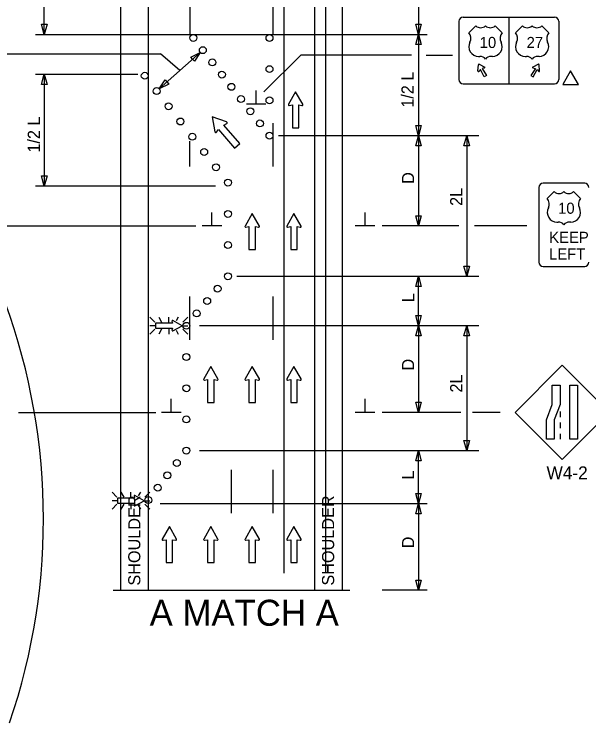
# Model space of a CAD drawing. Extents: x 16512 to 19504, y 5761 to 6984.
# Drawn here: x 16825.1 to 17156.7, y 5982.1 to 6390.9 of the extents above; entities that cross this region are included whole.
import ezdxf

# ---------------------------------------------------------------- set-up
doc = ezdxf.new("R2010")
doc.units = 0
for name, color, linetype in [('ALI_LEGAL_EX', 7, 'Continuous'), ('Level 3', 7, 'Continuous'), ('MT_SCRATCH_LEVEL_E', 7, 'Continuous'), ('PAVT_EDGE_EX', 7, 'Continuous'), ('TRAFFIC_SIGNS_PR', 7, 'Continuous'), ('TYPICAL_EX', 7, 'Continuous'), ('TYPICAL_TEXT_DIMEN_PR', 7, 'Continuous')]:
    doc.layers.add(name, color=color, linetype=linetype)

msp = doc.modelspace()

# ---------------------------------------------------------------- linework, layer by layer
at = {"layer": 'ALI_LEGAL_EX'}
for p, q in [((16980.68, 6984.25), (16980.68, 6166.11)), ((17004.68, 6984.25), (17004.68, 6166.11)), ((16980.68, 6932.34), (16980.68, 6068.43)), ((17004.68, 6932.34), (17004.68, 6068.43))]:
    msp.add_line(p, q, dxfattribs=at)
for points in [[(16974.45, 6302.95), (16974.45, 6327.95)], [(16926.45, 6302.95), (16926.45, 6317.59)], [(16926.45, 6202.95), (16926.45, 6227.95)], [(16974.45, 6202.95), (16974.45, 6227.95)], [(16950.45, 6102.95), (16950.45, 6127.95)], [(16974.45, 6102.95), (16974.45, 6127.95)]]:
    msp.add_lwpolyline(points, dxfattribs=at)
msp.add_arc((16477.95, 6099.7), 364, 341.1459, 21.3367, dxfattribs=at)
at = {"layer": 'Level 3'}
msp.add_line((16842.45, 6379.15), (16842.45, 6429.22), dxfattribs=at)
at = {"layer": 'MT_SCRATCH_LEVEL_E'}
for p, q in [((16987.48, 6346.14), (16983.37, 6338.9)), ((16991.62, 6338.9), (16987.48, 6346.14)), ((16983.85, 6338.22), (16985.63, 6338.53)), ((16985.63, 6338.53), (16985.63, 6325.28)), ((16989.37, 6325.28), (16989.37, 6338.53)), ((16989.37, 6338.53), (16991.15, 6338.22)), ((16985.63, 6325.28), (16989.37, 6325.28)), ((16962.45, 6275.9), (16958.33, 6268.66)), ((16962.45, 6275.9), (16958.33, 6268.66)), ((16966.59, 6268.66), (16962.45, 6275.9)), ((16966.59, 6268.66), (16962.45, 6275.9)), ((16986.5, 6275.9), (16982.39, 6268.66)), ((16986.5, 6275.9), (16982.39, 6268.66)), ((16990.65, 6268.66), (16986.5, 6275.9)), ((16990.65, 6268.66), (16986.5, 6275.9)), ((16958.82, 6267.97), (16960.59, 6268.29)), ((16958.82, 6267.97), (16960.59, 6268.29)), ((16960.59, 6268.29), (16960.59, 6255.03)), ((16960.59, 6268.29), (16960.59, 6255.03)), ((16964.34, 6255.03), (16964.34, 6268.29)), ((16964.34, 6268.29), (16966.11, 6267.97)), ((16964.34, 6255.03), (16964.34, 6268.29)), ((16964.34, 6268.29), (16966.11, 6267.97)), ((16982.87, 6267.97), (16984.65, 6268.29)), ((16982.87, 6267.97), (16984.65, 6268.29)), ((16984.65, 6268.29), (16984.65, 6255.03)), ((16984.65, 6268.29), (16984.65, 6255.03)), ((16988.39, 6255.03), (16988.39, 6268.29)), ((16988.39, 6268.29), (16990.17, 6267.97)), ((16988.39, 6255.03), (16988.39, 6268.29)), ((16988.39, 6268.29), (16990.17, 6267.97)), ((16960.59, 6255.03), (16964.34, 6255.03)), ((16960.59, 6255.03), (16964.34, 6255.03)), ((16984.65, 6255.03), (16988.39, 6255.03)), ((16984.65, 6255.03), (16988.39, 6255.03)), ((16938.54, 6187.65), (16934.43, 6180.41)), ((16942.69, 6180.41), (16938.54, 6187.65)), ((16962.45, 6187.65), (16958.33, 6180.41)), ((16966.59, 6180.41), (16962.45, 6187.65)), ((16986.5, 6187.65), (16982.39, 6180.41)), ((16990.65, 6180.41), (16986.5, 6187.65)), ((16934.91, 6179.73), (16936.69, 6180.04)), ((16936.69, 6180.04), (16936.69, 6166.78)), ((16940.43, 6166.78), (16940.43, 6180.04)), ((16940.43, 6180.04), (16942.21, 6179.73)), ((16958.82, 6179.73), (16960.59, 6180.04)), ((16960.59, 6180.04), (16960.59, 6166.78)), ((16964.34, 6166.78), (16964.34, 6180.04)), ((16964.34, 6180.04), (16966.11, 6179.73)), ((16982.87, 6179.73), (16984.65, 6180.04)), ((16984.65, 6180.04), (16984.65, 6166.78)), ((16988.39, 6166.78), (16988.39, 6180.04)), ((16988.39, 6180.04), (16990.17, 6179.73)), ((16936.69, 6166.78), (16940.43, 6166.78)), ((16960.59, 6166.78), (16964.34, 6166.78)), ((16984.65, 6166.78), (16988.39, 6166.78)), ((16914.64, 6095.33), (16910.53, 6088.09)), ((16918.78, 6088.09), (16914.64, 6095.33)), ((16938.54, 6095.33), (16934.43, 6088.09)), ((16942.69, 6088.09), (16938.54, 6095.33)), ((16962.45, 6095.33), (16958.33, 6088.09)), ((16966.59, 6088.09), (16962.45, 6095.33)), ((16986.5, 6095.33), (16982.39, 6088.09)), ((16990.65, 6088.09), (16986.5, 6095.33)), ((16911.01, 6087.41), (16912.79, 6087.72)), ((16912.79, 6087.72), (16912.79, 6074.47)), ((16916.53, 6074.47), (16916.53, 6087.72)), ((16916.53, 6087.72), (16918.31, 6087.41)), ((16934.91, 6087.41), (16936.69, 6087.72)), ((16936.69, 6087.72), (16936.69, 6074.47)), ((16940.43, 6074.47), (16940.43, 6087.72)), ((16940.43, 6087.72), (16942.21, 6087.41)), ((16958.82, 6087.41), (16960.59, 6087.72)), ((16960.59, 6087.72), (16960.59, 6074.47)), ((16964.34, 6074.47), (16964.34, 6087.72)), ((16964.34, 6087.72), (16966.11, 6087.41)), ((16982.87, 6087.41), (16984.65, 6087.72)), ((16984.65, 6087.72), (16984.65, 6074.47)), ((16988.39, 6074.47), (16988.39, 6087.72)), ((16988.39, 6087.72), (16990.17, 6087.41)), ((16912.79, 6074.47), (16916.53, 6074.47)), ((16936.69, 6074.47), (16940.43, 6074.47)), ((16960.59, 6074.47), (16964.34, 6074.47)), ((16984.65, 6074.47), (16988.39, 6074.47))]:
    msp.add_line(p, q, dxfattribs=at)
for centre, start, end in [((16983.77, 6338.68), 150.4248, 279.9638), ((16991.22, 6338.68), 260.0362, 29.7731), ((16958.74, 6268.43), 150.4248, 279.9638), ((16958.74, 6268.43), 150.4248, 279.9638), ((16966.18, 6268.43), 260.0362, 29.7731), ((16966.18, 6268.43), 260.0362, 29.7731), ((16982.8, 6268.43), 150.4248, 279.9638), ((16982.8, 6268.43), 150.4248, 279.9638), ((16990.24, 6268.43), 260.0362, 29.7731), ((16990.24, 6268.43), 260.0362, 29.7731), ((16934.84, 6180.19), 150.4248, 279.9638), ((16942.28, 6180.19), 260.0362, 29.7731), ((16958.74, 6180.19), 150.4248, 279.9638), ((16966.18, 6180.19), 260.0362, 29.7731), ((16982.8, 6180.19), 150.4248, 279.9638), ((16990.24, 6180.19), 260.0362, 29.7731), ((16910.93, 6087.87), 150.4248, 279.9638), ((16918.38, 6087.87), 260.0362, 29.7731), ((16934.84, 6087.87), 150.4248, 279.9638), ((16942.28, 6087.87), 260.0362, 29.7731), ((16958.74, 6087.87), 150.4248, 279.9638), ((16966.18, 6087.87), 260.0362, 29.7731), ((16982.8, 6087.87), 150.4248, 279.9638), ((16990.24, 6087.87), 260.0362, 29.7731)]:
    msp.add_arc(centre, 0.463, start, end, dxfattribs=at)
at = {"layer": 'PAVT_EDGE_EX'}
for p, q in [((16886.45, 6490.66), (16886.45, 6058.52)), ((16902.45, 6490.66), (16902.45, 6058.52)), ((16998.45, 6490.66), (16998.45, 6058.52)), ((17014.45, 6490.66), (17014.45, 6058.52))]:
    msp.add_line(p, q, dxfattribs=at)
msp.add_lwpolyline([(16974.45, 6479.22), (16926.45, 6479.22), (16926.45, 6379.15), (16974.45, 6379.15)], close=True, dxfattribs=at)
at = {"layer": 'TRAFFIC_SIGNS_PR'}
for p, q in [((17081.73, 6386.73), (17081.73, 6353.13)), ((17084.13, 6389.13), (17136.93, 6389.13)), ((17110.53, 6389.13), (17110.53, 6350.73)), ((17139.33, 6386.73), (17139.33, 6353.13)), ((17092.71, 6358.08), (17092.99, 6361.71)), ((17093.36, 6361.92), (17096.64, 6360.35)), ((17127.69, 6361.92), (17124.42, 6360.35)), ((17128.35, 6358.08), (17128.07, 6361.71)), ((17084.13, 6350.73), (17136.93, 6350.73)), ((17154.33, 6293.33), (17130.33, 6293.33)), ((17127.94, 6290.93), (17127.94, 6247.73)), ((17130.33, 6245.33), (17154.33, 6245.33)), ((16906.22, 6213.19), (16903.4, 6216.01)), ((16908.52, 6216.01), (16910.15, 6213.19)), ((16914.31, 6213.19), (16914.31, 6216.01)), ((16919.78, 6216.01), (16918.57, 6213.92)), ((16925.21, 6216.01), (16922.39, 6213.19)), ((16906.22, 6211.16), (16903.4, 6211.16)), ((16922.39, 6211.16), (16925.21, 6211.16)), ((16906.22, 6209.12), (16903.4, 6206.3)), ((16910.17, 6209.12), (16908.54, 6206.3)), ((16914.31, 6209.12), (16914.31, 6206.3)), ((16918.49, 6208.49), (16919.75, 6206.3)), ((16925.21, 6206.31), (16922.39, 6209.12)), ((17141.36, 6188.31), (17114.21, 6161.16)), ((17168.51, 6161.16), (17141.36, 6188.31)), ((17114.21, 6161.16), (17141.36, 6134.01)), ((17140.11, 6161.65), (17140.11, 6158.45)), ((17141.36, 6134.01), (17168.51, 6161.16)), ((17140.11, 6155.25), (17140.11, 6152.05)), ((17140.11, 6148.85), (17140.11, 6145.65)), ((16884.35, 6112.24), (16881.53, 6115.06)), ((16886.65, 6115.06), (16888.27, 6112.24)), ((16892.43, 6112.24), (16892.43, 6115.06)), ((16897.9, 6115.06), (16896.69, 6112.96)), ((16903.34, 6115.05), (16900.52, 6112.24)), ((16884.35, 6110.2), (16881.53, 6110.2)), ((16884.35, 6108.17), (16881.53, 6105.35)), ((16888.3, 6108.17), (16886.67, 6105.35)), ((16892.43, 6108.17), (16892.43, 6105.35)), ((16896.62, 6107.54), (16897.88, 6105.35)), ((16900.52, 6110.2), (16903.34, 6110.2)), ((16903.34, 6105.35), (16900.52, 6108.17))]:
    msp.add_line(p, q, dxfattribs=at)
for points in [[(17096.6, 6359.87), (17095.19, 6359.48), (17097.71, 6355.5), (17096.38, 6354.73), (17094.19, 6358.9), (17093.15, 6357.88)], [(17124.46, 6359.87), (17125.87, 6359.48), (17123.35, 6355.5), (17124.68, 6354.73), (17126.87, 6358.9), (17127.91, 6357.88)], [(16916.13, 6213.84), (16916.36, 6212.54), (16906.64, 6212.54), (16906.64, 6209.8), (16916.36, 6209.8), (16916.13, 6208.5)], [(16916.63, 6208.14), (16921.94, 6211.16), (16916.63, 6214.2)], [(16894.26, 6112.89), (16894.49, 6111.59), (16884.77, 6111.59), (16884.77, 6108.85), (16894.49, 6108.85), (16894.26, 6107.54)], [(16894.76, 6107.19), (16900.07, 6110.2), (16894.76, 6113.25)]]:
    msp.add_lwpolyline(points, dxfattribs=at)
for points in [[(17140.11, 6176.9), (17140.11, 6165.72), (17136.77, 6156.83), (17136.77, 6145.65), (17132.27, 6145.65), (17132.27, 6156.83), (17135.62, 6165.72), (17135.62, 6176.9)], [(17150.25, 6176.9), (17150.25, 6145.65), (17145.76, 6145.65), (17145.76, 6176.9)]]:
    msp.add_lwpolyline(points, close=True, dxfattribs=at)
for centre in [(16928.45, 6377.15), (16928.45, 6377.15), (16972.44, 6377.15), (16933.95, 6370.1), (16939.44, 6363.05), (16972.44, 6359.15), (16900.45, 6355.31), (16944.94, 6356), (16907.3, 6346.52), (16950.43, 6348.95), (16955.93, 6341.9), (16972.44, 6341.15), (16914.16, 6337.72), (16961.42, 6334.86), (16921.02, 6328.93), (16966.92, 6327.81), (16927.87, 6320.13), (16972.42, 6320.76), (16934.73, 6311.34), (16941.59, 6302.55), (16948.44, 6293.7), (16948.44, 6275.65), (16948.44, 6257.65), (16948.44, 6239.65), (16942.44, 6232.51), (16936.44, 6225.37), (16930.44, 6218.23), (16924.44, 6211.09), (16924.44, 6193.09), (16924.44, 6175.09), (16924.44, 6157.09), (16924.44, 6139.09), (16918.95, 6131.95), (16913.45, 6124.83), (16907.95, 6117.7), (16902.46, 6110.57)]:
    msp.add_circle(centre, 2, dxfattribs=at)
for centre, radius, start, end in [((17084.13, 6386.73), 2.4, 90, 180), ((17084.13, 6386.73), 2.4, 90, 180), ((17136.93, 6386.73), 2.4, 0, 90), ((17093.25, 6361.69), 0.26, 64.4823, 175.5177), ((17127.81, 6361.69), 0.26, 4.4823, 115.5177), ((17092.97, 6358.06), 0.26, 175.5177, 314.0115), ((17096.53, 6360.12), 0.26, 285.9885, 64.4823), ((17124.53, 6360.12), 0.26, 115.5177, 254.0115), ((17128.09, 6358.06), 0.26, 225.9885, 4.4823), ((17084.13, 6353.13), 2.4, 180, 270), ((17136.93, 6353.13), 2.4, 270, 0), ((17130.33, 6290.93), 2.4, 90, 180), ((17154.33, 6290.93), 2.4, 0, 90), ((17130.33, 6247.73), 2.4, 180, 270), ((17154.33, 6247.73), 2.4, 270, 0), ((16916.47, 6213.9), 0.341, 61.4833, 189.9593), ((16916.47, 6208.44), 0.341, 170.7308, 298.8916), ((16894.6, 6112.95), 0.341, 61.4833, 189.9593), ((16894.6, 6107.49), 0.341, 170.7308, 298.8916)]:
    msp.add_arc(centre, radius, start, end, dxfattribs=at)
at = {"layer": 'TYPICAL_EX'}
for p, q in [((17087.48, 6380.13), (17091.48, 6384.13)), ((17106.68, 6380.13), (17102.68, 6384.13)), ((17114.38, 6380.13), (17118.38, 6384.13)), ((17133.58, 6380.13), (17129.58, 6384.13)), ((17093.07, 6366.52), (17093.87, 6366.52)), ((17101.09, 6366.52), (17100.29, 6366.52)), ((17119.97, 6366.52), (17120.77, 6366.52)), ((17127.99, 6366.52), (17127.19, 6366.52)), ((17132.74, 6284.53), (17136.74, 6288.53)), ((17151.94, 6284.53), (17147.94, 6288.53)), ((17138.33, 6270.92), (17139.13, 6270.92)), ((17146.34, 6270.92), (17145.54, 6270.92))]:
    msp.add_line(p, q, dxfattribs=at)
for centre, radius, start, end in [((17094.28, 6387.05), 4.04, 226.1404, 313.8596), ((17099.88, 6387.05), 4.04, 226.1404, 313.8596), ((17121.18, 6387.05), 4.04, 226.1404, 313.8596), ((17126.78, 6387.05), 4.04, 226.1404, 313.8596), ((17083.69, 6376.93), 4.96, 333.0977, 40.1936), ((17110.47, 6376.93), 4.96, 139.8064, 206.9023), ((17110.59, 6376.93), 4.96, 333.0977, 40.1936), ((17137.37, 6376.93), 4.96, 139.8064, 206.9023), ((17093.08, 6372.12), 5.59, 152.6698, 269.9013), ((17101.08, 6372.12), 5.59, 270.0987, 27.3302), ((17119.98, 6372.12), 5.59, 152.6698, 269.9013), ((17127.97, 6372.12), 5.59, 270.0987, 27.3302), ((17093.88, 6362.52), 4.01, 37.1038, 90.1385), ((17100.28, 6362.52), 4.01, 89.8615, 142.8962), ((17120.78, 6362.52), 4.01, 37.1038, 90.1385), ((17127.17, 6362.52), 4.01, 89.8615, 142.8962), ((17139.54, 6291.45), 4.04, 226.1404, 313.8596), ((17145.13, 6291.45), 4.04, 226.1404, 313.8596), ((17128.94, 6281.33), 4.96, 333.0977, 40.1936), ((17155.73, 6281.33), 4.96, 139.8064, 206.9023), ((17138.34, 6276.52), 5.59, 152.6698, 269.9013), ((17146.33, 6276.52), 5.59, 270.0987, 27.3302), ((17139.14, 6266.92), 4.01, 37.1038, 90.1385), ((17145.53, 6266.92), 4.01, 89.8615, 142.8962)]:
    msp.add_arc(centre, radius, start, end, dxfattribs=at)
at = {"layer": 'TYPICAL_TEXT_DIMEN_PR'}
for p, q in [((17058.45, 6429.22), (17058.45, 6379.15)), ((16842.45, 6379.15), (16840.88, 6385.01)), ((16840.88, 6385.01), (16842.45, 6385.01)), ((16842.45, 6385.01), (16844.02, 6385.01)), ((16844.02, 6385.01), (16842.45, 6379.15)), ((17058.45, 6379.15), (17056.88, 6385.01)), ((17056.88, 6385.01), (17058.45, 6385.01)), ((17058.45, 6385.01), (17060.02, 6385.01)), ((17060.02, 6385.01), (17058.45, 6379.15)), ((16837.45, 6379.15), (17063.45, 6379.15)), ((17056.88, 6373.29), (17058.45, 6379.15)), ((17058.45, 6379.15), (17058.45, 6320.76)), ((17058.45, 6379.15), (17060.02, 6373.29)), ((17058.45, 6373.29), (17056.88, 6373.29)), ((17060.02, 6373.29), (17058.45, 6373.29)), ((16816.88, 6368.07), (16909.5, 6368.07)), ((16932.45, 6368.77), (16908.8, 6347.84)), ((16920.63, 6358.31), (16909.5, 6368.07)), ((16927.02, 6366.06), (16932.45, 6368.77)), ((16928.06, 6364.89), (16927.02, 6366.06)), ((16929.1, 6363.71), (16928.06, 6364.89)), ((16932.45, 6368.77), (16929.1, 6363.71)), ((16969.12, 6346.09), (16990.46, 6367.29)), ((17054.35, 6367.29), (16990.46, 6367.29)), ((17062.85, 6367.29), (17078.05, 6367.29)), ((16837.45, 6356.21), (16896.35, 6356.21)), ((16840.88, 6350.35), (16842.45, 6356.21)), ((16842.45, 6356.21), (16842.45, 6291.7)), ((16842.45, 6356.21), (16844.02, 6350.35)), ((16908.8, 6347.84), (16912.15, 6352.91)), ((16912.15, 6352.91), (16913.19, 6351.73)), ((16842.45, 6350.35), (16840.88, 6350.35)), ((16844.02, 6350.35), (16842.45, 6350.35)), ((16914.23, 6350.55), (16908.8, 6347.84)), ((16913.19, 6351.73), (16914.23, 6350.55)), ((16964.72, 6339.03), (16964.72, 6346.81)), ((16970.35, 6339.03), (16959.1, 6339.03)), ((16947.63, 6328.76), (16939.24, 6331.73)), ((16939.24, 6331.73), (16940.96, 6323.02)), ((16941.83, 6322.8), (16943.04, 6324.29)), ((16943.04, 6324.29), (16952.27, 6313.58)), ((16946.07, 6326.89), (16947.72, 6327.88)), ((16955.3, 6316.18), (16946.07, 6326.89)), ((17058.45, 6320.76), (17056.88, 6326.62)), ((17056.88, 6326.62), (17058.45, 6326.62)), ((17058.45, 6326.62), (17060.02, 6326.62)), ((17060.02, 6326.62), (17058.45, 6320.76)), ((17093.24, 6320.76), (16977.64, 6320.76)), ((17056.88, 6314.9), (17058.45, 6320.76)), ((17058.45, 6320.76), (17060.02, 6314.9)), ((17058.45, 6320.76), (17058.45, 6268.75)), ((17084.68, 6314.9), (17086.25, 6320.76)), ((17086.25, 6320.76), (17086.25, 6239.65)), ((17086.25, 6320.76), (17087.82, 6314.9)), ((16952.27, 6313.58), (16955.3, 6316.18)), ((17058.45, 6314.9), (17056.88, 6314.9)), ((17060.02, 6314.9), (17058.45, 6314.9)), ((17086.25, 6314.9), (17084.68, 6314.9)), ((17087.82, 6314.9), (17086.25, 6314.9)), ((16842.45, 6291.7), (16840.88, 6297.56)), ((16840.88, 6297.56), (16842.45, 6297.56)), ((16842.45, 6297.56), (16844.02, 6297.56)), ((16844.02, 6297.56), (16842.45, 6291.7)), ((16941.33, 6291.7), (16837.45, 6291.7)), ((16939.2, 6268.75), (16939.2, 6276.54)), ((17027.57, 6268.75), (17027.57, 6276.54)), ((17058.45, 6268.75), (17056.88, 6274.62)), ((17056.88, 6274.62), (17058.45, 6274.62)), ((17058.45, 6274.62), (17060.02, 6274.62)), ((17060.02, 6274.62), (17058.45, 6268.75)), ((16820.82, 6268.75), (16929.95, 6268.75)), ((16944.82, 6268.75), (16933.57, 6268.75)), ((17033.2, 6268.75), (17021.95, 6268.75)), ((17081.61, 6268.75), (17037.45, 6268.75)), ((17120.94, 6268.75), (17090.76, 6268.75)), ((17086.25, 6239.65), (17084.68, 6245.51)), ((17084.68, 6245.51), (17086.25, 6245.51)), ((17086.25, 6245.51), (17087.82, 6245.51)), ((17087.82, 6245.51), (17086.25, 6239.65)), ((16953.49, 6239.65), (17093.24, 6239.65)), ((17056.88, 6233.79), (17058.45, 6239.65)), ((17058.45, 6211.09), (17058.45, 6239.65)), ((17058.45, 6239.65), (17060.02, 6233.79)), ((17058.45, 6233.79), (17056.88, 6233.79)), ((17060.02, 6233.79), (17058.45, 6233.79)), ((17058.45, 6211.09), (17056.88, 6216.95)), ((17056.88, 6216.95), (17058.45, 6216.95)), ((17058.45, 6216.95), (17060.02, 6216.95)), ((17060.02, 6216.95), (17058.45, 6211.09)), ((17093.24, 6211.09), (16931.95, 6211.09)), ((17056.88, 6205.22), (17058.45, 6211.09)), ((17058.45, 6211.09), (17058.45, 6161.09)), ((17058.45, 6211.09), (17060.02, 6205.22)), ((17084.68, 6205.22), (17086.25, 6211.09)), ((17086.25, 6211.09), (17087.82, 6205.22)), ((17086.25, 6211.09), (17086.25, 6139.09)), ((17058.45, 6205.22), (17056.88, 6205.22)), ((17060.02, 6205.22), (17058.45, 6205.22)), ((17086.25, 6205.22), (17084.68, 6205.22)), ((17087.82, 6205.22), (17086.25, 6205.22)), ((16915.73, 6161.09), (16915.73, 6168.87)), ((17027.57, 6161.09), (17027.57, 6168.87)), ((17058.45, 6161.09), (17056.88, 6166.95)), ((17056.88, 6166.95), (17058.45, 6166.95)), ((17058.45, 6166.95), (17060.02, 6166.95)), ((17060.02, 6166.95), (17058.45, 6161.09)), ((16827.54, 6161.09), (16906.74, 6161.09)), ((16921.36, 6161.09), (16910.11, 6161.09)), ((17033.2, 6161.09), (17021.95, 6161.09)), ((17082.83, 6161.09), (17037.45, 6161.09)), ((17105.6, 6161.09), (17089.54, 6161.09)), ((17086.25, 6139.09), (17084.68, 6144.95)), ((17084.68, 6144.95), (17086.25, 6144.95)), ((17086.25, 6144.95), (17087.82, 6144.95)), ((17087.82, 6144.95), (17086.25, 6139.09)), ((16931.95, 6139.09), (17093.24, 6139.09)), ((17056.88, 6133.22), (17058.45, 6139.09)), ((17058.45, 6108.52), (17058.45, 6139.09)), ((17058.45, 6139.09), (17060.02, 6133.22)), ((17058.45, 6133.22), (17056.88, 6133.22)), ((17060.02, 6133.22), (17058.45, 6133.22)), ((17058.45, 6108.52), (17056.88, 6114.38)), ((17056.88, 6114.38), (17058.45, 6114.38)), ((17058.45, 6114.38), (17060.02, 6114.38)), ((17060.02, 6114.38), (17058.45, 6108.52)), ((16909.4, 6108.52), (17063.45, 6108.52)), ((17056.88, 6102.66), (17058.45, 6108.52)), ((17058.45, 6108.52), (17058.45, 6058.52)), ((17058.45, 6108.52), (17060.02, 6102.66)), ((17058.45, 6102.66), (17056.88, 6102.66)), ((17060.02, 6102.66), (17058.45, 6102.66)), ((17058.45, 6058.52), (17056.88, 6064.38)), ((17056.88, 6064.38), (17058.45, 6064.38)), ((17058.45, 6064.38), (17060.02, 6064.38)), ((17060.02, 6064.38), (17058.45, 6058.52)), ((16882.15, 6058.52), (17018.8, 6058.52)), ((17063.45, 6058.52), (17037.45, 6058.52))]:
    msp.add_line(p, q, dxfattribs=at)
msp.add_lwpolyline([(17146.22, 6358.11), (17141.69, 6350.28), (17150.74, 6350.28)], close=True, dxfattribs=at)
for centre, start, end in [((16947.46, 6328.3), 300.7803, 70.5173), ((16941.45, 6323.12), 191.169, 320.708)]:
    msp.add_arc(centre, 0.494, start, end, dxfattribs=at)

# ---------------------------------------------------------------- texts
at = {"layer": 'TRAFFIC_SIGNS_PR'}
for s, height, p in [('10', 6.4, (17093.74, 6371.33)), ('27', 6.4, (17120.81, 6371.33)), ('10', 6.4, (17138.99, 6275.73)), ('KEEP', 6.4, (17133.87, 6258.93)), ('LEFT', 6.4, (17133.78, 6249.33)), ('W4-2', 7.44, (17132.32, 6122.57))]:
    msp.add_text(s, height=height, dxfattribs=at).set_placement(p)
at = {"layer": 'TYPICAL_TEXT_DIMEN_PR'}
for s, p in [('1/2 L', (17055.59, 6336.89)), ('1/2 L', (16839.89, 6311)), ('D', (17055.89, 6292.97)), ('2L', (17083.69, 6280.26)), ('L', (17055.98, 6224.72)), ('D', (17055.89, 6185.3)), ('2L', (17083.69, 6172.59)), ('L', (17055.89, 6122.38)), ('SHOULDER', (16897.88, 6061.23)), ('SHOULDER', (17009.74, 6061.23)), ('D', (17055.89, 6082.74))]:
    msp.add_text(s, height=7, rotation=90, dxfattribs=at).set_placement(p)
msp.add_text('A MATCH A', height=15, dxfattribs=at).set_placement((16903.24, 6038.06))

doc.saveas('drawing.dxf')
